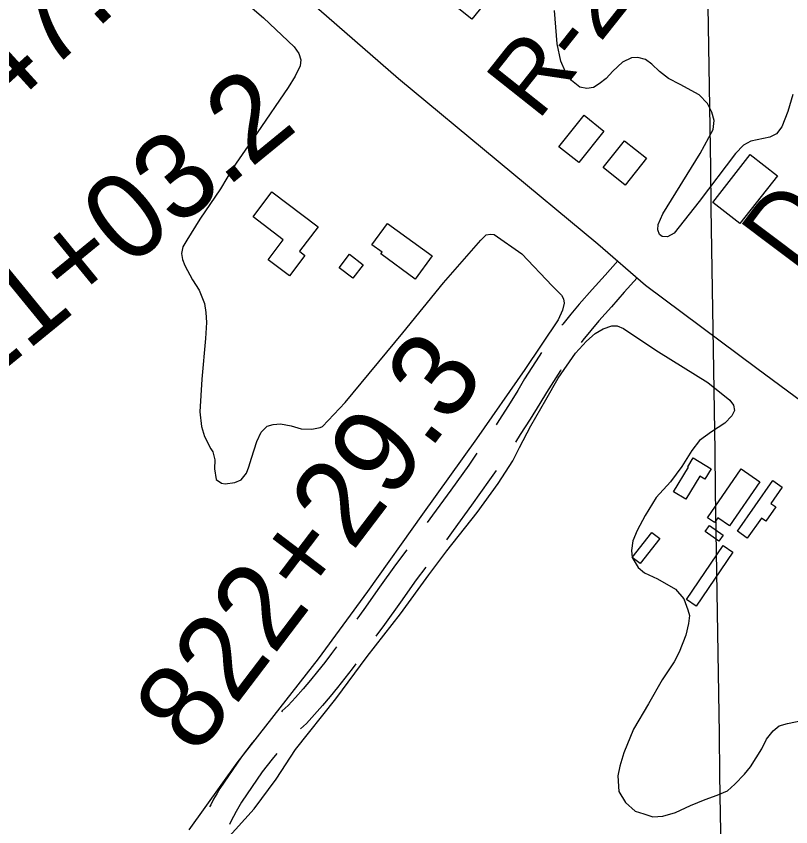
# Model space of a CAD drawing. Extents: x 3823584 to 3861785, y 301729 to 327625.
# Drawn here: x 3837389 to 3838296, y 322453 to 323402 of the extents above; entities that cross this region are included whole.
import ezdxf

# ---------------------------------------------------------------- set-up
doc = ezdxf.new("R2010")
doc.units = 0
for name, color, linetype in [('V-BLDG-OTLN', 7, 'Continuous'), ('V-GRID-MAJR', 7, 'Continuous'), ('V-RIVR-EDGE', 7, 'Continuous'), ('V-RIVR-RANG-IDEN', 7, 'Continuous'), ('V-ROAD-CNTR', 7, 'Continuous'), ('V-SITE-VEGE', 7, 'Continuous'), ('V-SURV-IDEN', 7, 'Continuous')]:
    doc.layers.add(name, color=color, linetype=linetype)

msp = doc.modelspace()

# ---------------------------------------------------------------- linework, layer by layer
at = {"layer": 'V-BLDG-OTLN'}
for points in [[(3837922.269, 323398.243), (3837897.261, 323417.955), (3837895.333, 323415.51), (3837890.082, 323419.647), (3837886.6520000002, 323415.295), (3837864.531, 323432.729), (3837907.109, 323486.749), (3837931.585, 323467.455), (3837930.487, 323466.063), (3837945.978, 323453.855), (3837928.308, 323431.43700000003), (3837940.721, 323421.654)], [(3838024.216, 323248.645), (3838053.582, 323285.499), (3838076.862, 323266.94800000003), (3838047.4960000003, 323230.094)], [(3838126.811, 323235.165), (3838101.774, 323203.773), (3838075.94, 323224.376), (3838100.9790000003, 323255.768)], [(3838280.003, 323214.72000000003), (3838236.119, 323158.643), (3838204.2660000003, 323183.572), (3838248.1550000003, 323239.646)], [(3837665.9590000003, 323166.498), (3837688.068, 323195.78), (3837742.02, 323155.043), (3837720.324, 323126.308), (3837726.619, 323121.552), (3837708.64, 323097.74), (3837683.818, 323116.477), (3837701.39, 323139.749)], [(3837855.864, 323093.775), (3837815.525, 323123.15), (3837816.977, 323125.142), (3837805.103, 323133.793), (3837823.365, 323158.873), (3837875.58, 323120.852)], [(3837782.648, 323094.723), (3837766.727, 323106.909), (3837778.8880000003, 323122.797), (3837794.809, 323110.614)], [(3838181.378, 322884.465), (3838202.376, 322871.528), (3838194.964, 322859.498), (3838189.336, 322862.963), (3838172.665, 322835.903), (3838158.204, 322844.81200000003), (3838175.8850000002, 322873.511), (3838174.973, 322874.072)], [(3838259.363, 322856.539), (3838223.859, 322805.021), (3838210.379, 322814.309), (3838206.429, 322808.577), (3838198.208, 322814.242), (3838237.661, 322871.495)], [(3838233.202, 322798.624), (3838274.762, 322857.905), (3838285.703, 322850.235), (3838272.307, 322831.127), (3838278.199, 322826.999), (3838266.5330000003, 322810.36100000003), (3838261.315, 322814.018), (3838244.8140000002, 322790.483)], [(3838142.1520000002, 322789.922), (3838119.129, 322760.59), (3838109.894, 322767.84), (3838132.918, 322797.17100000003)], [(3838211.561, 322786.95), (3838195.574, 322798.335), (3838200.639, 322805.443), (3838216.626, 322794.056)], [(3838173.558, 322718.57300000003), (3838216.6580000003, 322781.875), (3838228.025, 322774.136), (3838184.921, 322710.836)]]:
    msp.add_lwpolyline(points, close=True, dxfattribs=at)
at = {"layer": 'V-GRID-MAJR'}
msp.add_spline([(3838444.8910000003, 307319.343), (3838352.38, 313376.366), (3838259.823, 319436.473), (3838167.2660000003, 325496.576), (3838167.219, 325499.664)], degree=3, dxfattribs=at)
at = {"layer": 'V-RIVR-EDGE'}
msp.add_spline([(3836304.3756208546, 325474.18490968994), (3836346.414637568, 325438.3248399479), (3836389.407230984, 325406.0749957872), (3836417.6425015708, 325385.4333151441), (3836442.6682071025, 325366.7281829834), (3836470.247893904, 325340.94515767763), (3836497.8244014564, 325313.8763988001), (3836554.9028376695, 325258.4483785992), (3836598.5128638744, 325215.91107623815), (3836636.356164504, 325181.10248193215), (3836681.25510353, 325139.84773389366), (3836737.070060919, 325093.42302794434), (3836790.9421113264, 325041.2172897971), (3836840.3252216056, 324993.52274652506), (3836889.068644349, 324947.1155264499), (3836934.613629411, 324907.1449223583), (3836980.8110190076, 324871.0299293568), (3837015.471778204, 324849.0866188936), (3837040.494304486, 324829.09575316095), (3837085.3916538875, 324787.1981383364), (3837143.7621821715, 324734.3384060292), (3837181.60866205, 324700.815545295), (3837223.2932671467, 324659.5687453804), (3837272.052586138, 324619.5901931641), (3837314.3832372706, 324579.6275371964), (3837346.4455057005, 324546.7618498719), (3837364.398086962, 324527.4313367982), (3837395.83179523, 324500.35304017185), (3837442.024415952, 324462.30944681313), (3837492.7139249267, 324422.9689925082), (3837554.3051456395, 324372.67277922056), (3837573.562535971, 324361.05348832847), (3837583.2007688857, 324359.1010435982), (3837596.685075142, 324352.6389936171), (3837621.0774516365, 324337.7926517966), (3837648.0333471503, 324319.7256175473), (3837677.5368654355, 324292.00922300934), (3837718.5754244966, 324249.4782791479), (3837753.847257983, 324214.6760433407), (3837781.426944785, 324188.89301803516), (3837800.047826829, 324179.8467839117), (3837819.9544424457, 324170.79737053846), (3837850.7214395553, 324134.0776617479), (3837874.448694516, 324110.2327745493), (3837909.0728923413, 324073.5035280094), (3837941.7780275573, 324040.63625106), (3837989.872225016, 323991.65915346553), (3838022.5821291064, 323960.7204768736), (3838034.1219387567, 323947.83452790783), (3838046.301435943, 323933.66125574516), (3838066.8302532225, 323916.25298453), (3838089.9146413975, 323892.40968695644), (3838140.5946126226, 323849.2120319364), (3838186.144366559, 323811.1700282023), (3838215.652653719, 323785.38223402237), (3838265.675451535, 323736.40036755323), (3838297.1043909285, 323707.3934705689), (3838336.8747022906, 323671.9372406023), (3838359.952731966, 323645.5224758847), (3838385.6228939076, 323627.4586208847), (3838404.2374174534, 323615.8409196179), (3838421.5598489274, 323601.65493045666), (3838441.441030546, 323582.31964850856), (3838460.0476059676, 323567.48761331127), (3838468.395336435, 323563.60974747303), (3838484.446340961, 323555.21273863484), (3838548.5883636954, 323496.55289863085), (3838595.4381578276, 323464.2935167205), (3838649.9785090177, 323422.37205752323), (3838701.302936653, 323379.8156796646), (3838749.433695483, 323345.62451814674), (3838798.2232173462, 323317.86043486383), (3838856.617590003, 323274.6437043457), (3838932.9883882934, 323221.7394625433), (3838989.4684672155, 323184.31330197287), (3839037.599226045, 323150.12214045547), (3839068.4186807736, 323134.6170356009), (3839093.417362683, 323104.98316807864), (3839110.730256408, 323086.93997820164), (3839122.930418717, 323081.1239742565), (3839143.464004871, 323065.6443033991), (3839172.3405526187, 323044.35816634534), (3839190.955076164, 323032.7404650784), (3839215.98555057, 323015.9639332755), (3839242.319244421, 323006.25575686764), (3839316.801182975, 322969.42795358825), (3839341.8396055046, 322955.86575571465), (3839371.3828644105, 322944.2210308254), (3839391.2910696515, 322935.81448423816), (3839417.6104568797, 322920.32050675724), (3839461.26181333, 322894.4977408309), (3839483.709693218, 322873.22750002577), (3839520.2990527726, 322851.27942068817), (3839555.6010891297, 322828.6916538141), (3839599.9048501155, 322806.7244989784), (3839718.698497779, 322751.1438747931), (3839768.138834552, 322726.5925358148), (3839807.9457072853, 322705.9222419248), (3839836.8508682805, 322696.20770701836), (3839865.0988558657, 322680.7089606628), (3839887.567400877, 322667.7959880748), (3839924.172656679, 322652.2765765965), (3839969.7621512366, 322630.306242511), (3840004.4324481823, 322612.2201327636), (3840037.8249596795, 322597.35153619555), (3840085.3541819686, 322579.87650073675), (3840108.4624145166, 322565.6762049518), (3840121.9212867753, 322548.928286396), (3840123.184765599, 322539.92497214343), (3840122.5260025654, 322533.4978939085), (3840117.9957321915, 322521.29455234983), (3840112.8353120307, 322514.2357347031), (3840095.465191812, 322509.1357202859), (3840089.6793907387, 322509.1500269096), (3840085.168195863, 322504.661086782), (3840084.5094328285, 322498.2340085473), (3840085.779270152, 322491.8021614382), (3840130.719539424, 322467.2619498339), (3840169.888314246, 322448.52184592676), (3840197.5093312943, 322439.45335705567), (3840209.076164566, 322437.4961434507), (3840231.586039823, 322441.2977072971), (3840246.3910513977, 322448.9755473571), (3840266.343766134, 322458.5692707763), (3840273.434376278, 322466.26618633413), (3840278.590027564, 322471.3964036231), (3840288.898150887, 322480.37110462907), (3840295.9808129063, 322484.8536862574), (3840301.7666139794, 322484.8393796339), (3840308.195281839, 322484.8234833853), (3840320.395444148, 322479.00747944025), (3840324.873256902, 322469.99621706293), (3840326.781192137, 322461.6341799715), (3840338.324181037, 322450.0339645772), (3840344.7401318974, 322444.87513404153), (3840366.580116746, 322437.7495521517), (3840385.842275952, 322428.05886161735), (3840421.7967168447, 322409.3267058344), (3840466.0957089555, 322385.43095064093), (3840492.411916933, 322368.65123958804), (3840506.526372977, 322357.0446656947), (3840533.4854477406, 322340.2633650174), (3840559.1778644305, 322331.1996450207), (3840587.441748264, 322322.12956652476), (3840611.8452521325, 322311.78329220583), (3840642.0218400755, 322296.27977697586), (3840678.615968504, 322276.2602979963), (3840712.637040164, 322255.60431073), (3840733.1753951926, 322242.05324023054), (3840784.5268464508, 322210.42559773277), (3840835.889425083, 322183.29802273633), (3840892.388579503, 322153.5862635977), (3840923.854080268, 322139.3653026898), (3840950.8242824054, 322127.08406951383), (3840989.3295253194, 322099.98828701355), (3841017.5727440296, 322082.56094030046), (3841061.238407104, 322062.5239754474), (3841092.6943701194, 322044.4458138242), (3841151.0982805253, 322005.0862840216), (3841210.7847452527, 321964.43784139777), (3841240.294622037, 321939.29291400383), (3841299.971549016, 321894.78727066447), (3841335.8926077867, 321862.55491237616), (3841374.3692374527, 321823.88752772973), (3841411.5712609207, 321789.72338983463), (3841444.922442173, 321758.1402568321), (3841469.94019958, 321736.22079074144), (3841482.124465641, 321723.9761189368), (3841496.2198461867, 321704.6551436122), (3841509.051747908, 321694.3374825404), (3841523.1773313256, 321687.23097614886), (3841573.8986327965, 321660.747857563), (3841623.970708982, 321631.69486145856), (3841667.623655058, 321606.5149623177), (3841696.5208679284, 321593.58609348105), (3841738.2626995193, 321575.48249786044), (3841787.074476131, 321556.7185495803), (3841815.992354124, 321552.1469489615), (3841851.3325414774, 321544.9879849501), (3841886.661601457, 321533.32895343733), (3841930.322495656, 321511.36338822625), (3841950.219573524, 321498.4567741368), (3841977.1818275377, 321482.9612070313), (3841998.380535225, 321476.4800815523), (3842052.9924195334, 321463.4876277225), (3842082.546805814, 321456.3429703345), (3842109.5185975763, 321444.7046039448), (3842146.1190845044, 321427.2565921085), (3842196.2006984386, 321402.06079671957), (3842241.1346092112, 321374.94911797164), (3842288.6336286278, 321345.2596135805), (3842321.375325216, 321327.17827270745), (3842366.940975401, 321295.56493683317), (3842395.188962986, 321280.06619047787), (3842429.2227516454, 321264.5531374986), (3842452.3516493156, 321258.7101099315), (3842470.9725313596, 321249.663875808)], degree=3, dxfattribs=at)
at = {"layer": 'V-ROAD-CNTR'}
for points in [[(3835362.231236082, 325460.9250527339), (3835509.512941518, 325334.346305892), (3835871.754217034, 325022.76592905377), (3836108.39574375, 324817.59833938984), (3836413.993132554, 324556.9258607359), (3836839.7512810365, 324193.6555872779), (3837163.6936331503, 323918.79213700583), (3837445.019070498, 323669.35663587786), (3837836.483287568, 323328.41131777), (3838069.5748213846, 323134.8777048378), (3838125.3817097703, 323086.7958010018), (3838255.977448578, 322989.4639956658), (3838600.004760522, 322735.3525038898), (3839019.3109219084, 322425.41512376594), (3839565.53882945, 322022.9139287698), (3840024.8789107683, 321675.2296241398), (3840474.8730107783, 321349.99327461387), (3840728.35650381, 321161.30865198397)], [(3838093.3375141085, 323115.0970615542), (3838078.3130529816, 323098.22065294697), (3838063.271064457, 323081.3826955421), (3838048.02279115, 323064.371855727), (3838038.207520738, 323052.6072717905), (3838028.6661470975, 323040.8128058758), (3838027.762271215, 323039.6594225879)], [(3838115.7444858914, 323095.14893844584), (3838100.7029470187, 323078.2533470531), (3838085.626935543, 323061.3773044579), (3838070.71720885, 323044.74414427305), (3838061.3884792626, 323033.5627282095), (3838052.1358529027, 323022.12519412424), (3838050.2151394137, 323019.6742836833)], [(3838003.8586326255, 323007.60772929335), (3838000.9606572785, 323003.35494714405), (3837992.3428407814, 322990.1535326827), (3837983.991319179, 322976.7864096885), (3837976.0426994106, 322963.4869482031), (3837965.012974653, 322945.68302281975), (3837953.7359993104, 322928.0072085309), (3837950.48566484, 322923.0561436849)], [(3838026.466372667, 322987.5098199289), (3838025.9193427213, 322986.707052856), (3838017.627159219, 322974.00446731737), (3838009.590680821, 322961.14159031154), (3838001.6713005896, 322947.8910517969), (3837990.411025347, 322929.71497718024), (3837978.9220006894, 322911.7067914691), (3837973.152613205, 322902.918584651)], [(3837928.2153812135, 322889.83087826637), (3837918.5304365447, 322875.8956887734), (3837897.528132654, 322846.53049005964), (3837876.2566066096, 322817.31278446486), (3837869.8347654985, 322808.6466300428)], [(3837950.794736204, 322869.75245851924), (3837943.049563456, 322858.6083112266), (3837921.8558673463, 322828.9755099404), (3837900.4353933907, 322799.5532155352), (3837892.336464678, 322788.6238627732)], [(3837845.921122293, 322776.58250338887), (3837832.8051628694, 322759.19046248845), (3837814.1948131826, 322732.89401625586), (3837795.5826994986, 322706.93656365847), (3837787.316850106, 322695.56257232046)], [(3837868.4055521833, 322756.57265137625), (3837857.0308371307, 322741.4895375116), (3837838.629186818, 322715.4879837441), (3837819.9073005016, 322689.37743634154), (3837809.8397089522, 322675.52420799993)], [(3837763.690618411, 322663.28627006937), (3837757.918245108, 322655.44632157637), (3837749.8356642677, 322644.86925017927), (3837741.565899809, 322634.4285499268), (3837733.11819196, 322624.1284294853), (3837724.4963503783, 322613.9751023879), (3837715.703437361, 322603.9727224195), (3837707.1070074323, 322594.5307574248), (3837700.174894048, 322588.174814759), (3837699.095382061, 322587.1335263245)], [(3837786.1990579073, 322643.2584782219), (3837781.9177548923, 322637.44367842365), (3837773.5143357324, 322626.4467498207), (3837764.9241001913, 322615.60145007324), (3837756.15180804, 322604.9055705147), (3837747.197649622, 322594.3608976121), (3837738.0625626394, 322583.9692775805), (3837728.3789925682, 322573.3332425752), (3837721.5855203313, 322567.10441773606)], [(3837671.4602298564, 322558.23736788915), (3837665.0977851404, 322550.7033399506), (3837658.672186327, 322542.68977595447), (3837652.3299809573, 322534.3545783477), (3837627.2164857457, 322497.4964179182), (3837623.336642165, 322491.13024941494), (3837619.724221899, 322484.768411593), (3837616.3185791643, 322478.2908448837), (3837615.1358534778, 322475.8606082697)], [(3837693.876028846, 322538.2838358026), (3837688.2642148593, 322531.6386600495), (3837682.315813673, 322524.2202240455), (3837676.680019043, 322516.8134216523), (3837652.437514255, 322481.2335820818), (3837649.195357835, 322475.9137505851), (3837646.051778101, 322470.377588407), (3837643.089420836, 322464.74315511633), (3837640.1121836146, 322458.6255988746), (3837638.422699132, 322455.3719537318)]]:
    msp.add_lwpolyline(points, dxfattribs=at)
at = {"layer": 'V-SITE-VEGE'}
for points in [[(3837606.316, 323461.369), (3837678.3170000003, 323399.703), (3837714.003, 323365.696), (3837719.609, 323357.73600000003), (3837721.845, 323350.488), (3837721.311, 323343.355), (3837715.394, 323331.493), (3837706.991, 323318.16000000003), (3837670.608, 323265.14400000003), (3837642.821, 323224.567), (3837627.901, 323199.53)], [(3838297.954, 323309.692), (3838292.191, 323290.092), (3838285.148, 323272.18700000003), (3838278.852, 323263.89400000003), (3838271, 323259.874), (3838248.7630000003, 323255.244), (3838240.2060000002, 323250.435), (3838230.931, 323240.869), (3838188.3710000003, 323184.499), (3838159.011, 323147.58400000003), (3838151.352, 323143.365), (3838145.1070000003, 323143.699), (3838141.947, 323145.897), (3838139.895, 323151.265), (3838140.43, 323157.806), (3838146.052, 323169.969), (3838189.488, 323240.906), (3838204.616, 323268.781), (3838206.167, 323279.283), (3838203.349, 323289.31200000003), (3838198.151, 323299.257), (3838188.593, 323309.526), (3838166.1550000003, 323321.748), (3838152.511, 323328.67100000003), (3838141.949, 323336.858), (3838132.977, 323345.43700000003), (3838125.373, 323350.738), (3838116.562, 323353.363), (3838109.026, 323352.81200000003), (3838098.786, 323347.617), (3838087.221, 323337.07300000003), (3838079.338, 323328.492), (3838071.3710000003, 323322.291), (3838064.506, 323317.968), (3838056.769, 323317.021), (3838048.647, 323318.555), (3838038.974, 323326.244), (3838031.4990000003, 323336.996), (3838026.412, 323349.021), (3838022.166, 323369.272), (3838019.018, 323408.256)], [(3837627.901, 323199.53), (3837603.711, 323163.985), (3837588.305, 323139.491), (3837583.898, 323131.389), (3837582.069, 323123.668), (3837583.417, 323116.522), (3837586.153, 323109.569), (3837595.176, 323092.866), (3837602.84, 323080.729), (3837608.894, 323065.232), (3837610.815, 323054.515), (3837611.343, 323043.015), (3837610.444, 323024.188), (3837605.81, 322976.636), (3837603.807, 322938.387), (3837605.494, 322921.13300000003), (3837609.193, 322909.414), (3837616.644, 322895.099), (3837618.802, 322891.51900000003), (3837621.129, 322882.188), (3837620.67, 322871.485), (3837622.779, 322858.984), (3837628.901, 322854.984), (3837633.458, 322854.165), (3837644.566, 322855.49), (3837651.918, 322858.62), (3837658.308, 322866.51300000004), (3837661.126, 322874.029), (3837663.9590000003, 322883.927), (3837670.215, 322903.516), (3837675.434, 322914.585), (3837682.411, 322921.485), (3837689.362, 322923.625), (3837698.0840000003, 322924.17), (3837710.563, 322921.915), (3837722.239, 322918.481), (3837734.725, 322918.014), (3837744.451, 322920.13800000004), (3837747.433, 322921.311), (3837773.7600000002, 322949.309), (3837841.231, 323030.994), (3837889.142, 323089.202), (3837932.648, 323139.503), (3837938.829, 323145.413), (3837943.988, 323146.374), (3837948.344, 323145.954), (3837980.727, 323123.369), (3838016.1, 323085.942), (3838027.333, 323074.778), (3838029.6920000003, 323070.502), (3838030.4560000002, 323065.738), (3838028.326, 323057.227), (3838023.2060000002, 323046.155), (3837984.3170000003, 322987.799), (3837927.751, 322906.846), (3837864.304, 322818.39900000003), (3837800.056, 322728.074), (3837742.116, 322649.21), (3837697.183, 322591.782), (3837647.058, 322527.542), (3837590.6070000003, 322448.868)], [(3837623.5270000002, 322424.958), (3837667.377, 322473.62200000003), (3837693.026, 322508.338), (3837715.804, 322542.865), (3837763.082, 322602.212), (3837799.612, 322652.009), (3837838.518, 322701.7), (3837871.757, 322747.36), (3837893.011, 322775.463), (3837928.4250000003, 322820.517), (3837952.981, 322854.54), (3837970.262, 322880.783), (3837977.876, 322896.387), (3837991.292, 322921.86), (3838008.897, 322952.55700000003), (3838023.1040000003, 322977.629), (3838043.6720000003, 323007.12), (3838056.626, 323020.911), (3838066.679, 323030.064), (3838075.822, 323035.655), (3838086.041, 323038.965), (3838092.279, 323038.829), (3838099.789, 323035.913), (3838102.5500000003, 323033.82), (3838140.93, 323008.742)], [(3838140.93, 323008.742), (3838198.6520000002, 322972.564), (3838224.4820000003, 322951.818), (3838228.707, 322946.14900000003), (3838229.958, 322940.001), (3838226.853, 322933.781), (3838218.5840000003, 322924.915), (3838202.681, 322914.907), (3838188.957, 322904.685), (3838179.682, 322893.151), (3838168.086, 322874.404), (3838154.911, 322856.455), (3838137.97, 322838.033), (3838125.076, 322817.015), (3838115.764, 322799.242), (3838110.545, 322787.19), (3838109.095, 322775.909), (3838109.8200000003, 322767.666), (3838116.806, 322756.257), (3838124.394, 322749.875), (3838139.605, 322742.75800000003)], [(3838139.605, 322742.75800000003), (3838160.699, 322730.59500000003), (3838170.531, 322719.454), (3838175.207, 322706.363), (3838177.151, 322700.018), (3838175.907, 322690.52400000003), (3838172.661, 322676.688), (3838165.026, 322656.93700000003), (3838159.024, 322645.49), (3838145.048, 322624.589), (3838129.051, 322596.572), (3838111.465, 322566.982), (3838100.219, 322538.939), (3838095.38, 322523.53), (3838093.336, 322512.059), (3838094.419, 322493.84), (3838102.2630000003, 322481.13), (3838113.29, 322470.77400000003), (3838123.565, 322467.55), (3838134.235, 322464.318), (3838145.72, 322465.045), (3838160.787, 322469.315), (3838178.252, 322477.528), (3838195.312, 322484.55700000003), (3838209.597, 322489.621), (3838221.502, 322494.69800000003), (3838230.255, 322502.567), (3838241.404, 322513.984), (3838248.5810000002, 322522.651), (3838261.768, 322543.955), (3838267.3710000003, 322555.006), (3838274.951, 322564.86100000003), (3838282.111, 322570.757), (3838292.021, 322573.471), (3838310.651, 322577.325)]]:
    msp.add_lwpolyline(points, dxfattribs=at)

# ---------------------------------------------------------------- texts
at = {"layer": 'V-RIVR-RANG-IDEN'}
for s, height, rotation, p in [('R-28.5', 82.99999799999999, 51.59333483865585, (3837999.360762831, 323277.77959259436)), ('D-110', 83.00000000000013, 53.06832571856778, (3838299.3000026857, 323101.38147424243))]:
    msp.add_text(s, height=height, rotation=rotation, dxfattribs=at).set_placement(p)
at = {"layer": 'V-SURV-IDEN'}
for s, rotation, p in [('818+47.1', 42.30833332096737, (3837148.657398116, 323081.768570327)), ('821+03.2', 39.26369872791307, (3837285.806112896, 322914.7691033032)), ('822+29.3', 52.768611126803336, (3837599.8939091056, 322533.89923593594))]:
    msp.add_text(s, height=100, rotation=rotation, dxfattribs=at).set_placement(p)

doc.saveas('drawing.dxf')
